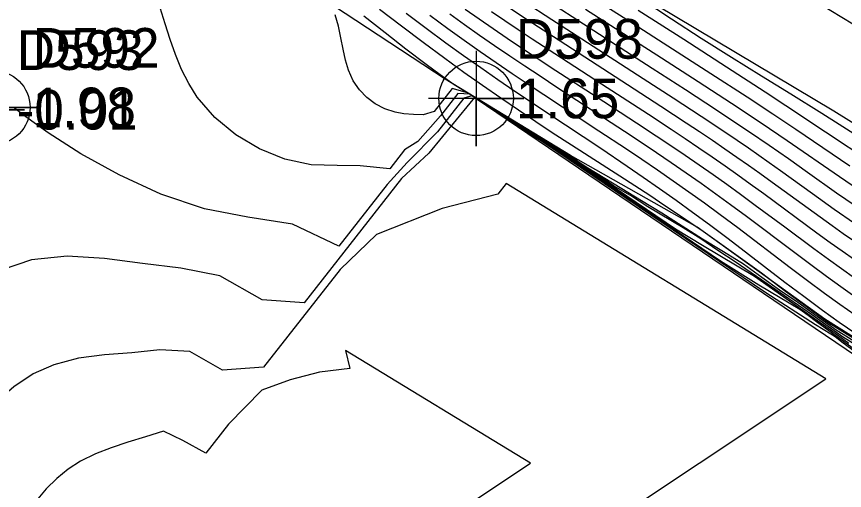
# Model space of a CAD drawing. Extents: x 2356077 to 2359823, y 225951 to 227822.
# Drawn here: x 2357257.6 to 2357309.7, y 226841 to 226870.8 of the extents above; entities that cross this region are included whole.
import ezdxf

# ---------------------------------------------------------------- set-up
doc = ezdxf.new("R2010")
doc.units = 0
for name, color, linetype in [('DTM Contours Major', 7, 'Continuous'), ('DTM Contours Minor', 7, 'Continuous'), ('Exist DTM Breakline', 7, 'Continuous'), ('Exist DTM Breakline Cogo Elevation', 7, 'Continuous'), ('Exist DTM Breakline Cogo Number', 7, 'Continuous'), ('Exist DTM Breakline Cogo Point CELL', 7, 'Continuous'), ('Exist DTM Breakline Underwater Cogo Elevation', 7, 'Continuous'), ('Exist DTM Breakline Underwater Cogo Number', 7, 'Continuous'), ('Exist DTM Breakline Underwater Cogo Point CELL', 7, 'Continuous'), ('Exist DTM Regular Point CELL', 7, 'Continuous'), ('Exist DTM Regular Point Cogo Elevation', 7, 'Continuous'), ('Exist DTM Regular Point Cogo Number', 7, 'Continuous'), ('Exist Roads EOP', 7, 'Continuous'), ('PH Exist DTM Breakline', 7, 'Continuous')]:
    doc.layers.add(name, color=color, linetype=linetype)

msp = doc.modelspace()

# ---------------------------------------------------------------- linework, layer by layer
at = {"layer": 'DTM Contours Major'}
for points in [[(2357310.359, 226856.666), (2357309.651, 226857.159), (2357308.958, 226857.65), (2357308.199, 226858.196), (2357305.194, 226860.391), (2357304.42, 226860.948), (2357303.706, 226861.454), (2357302.972, 226861.967), (2357302.214, 226862.489), (2357301.432, 226863.022), (2357300.62, 226863.567), (2357299.777, 226864.128), (2357298.178, 226865.178), (2357296.505, 226866.264), (2357291.422, 226869.548), (2357289.833, 226870.588), (2357288.221, 226871.662)], [(2357310.446, 226850.853), (2357309.405, 226851.576), (2357308.356, 226852.328), (2357307.176, 226853.2), (2357305.989, 226854.098), (2357302.421, 226856.836), (2357301.24, 226857.726), (2357300.185, 226858.504), (2357299.14, 226859.259), (2357298.104, 226859.992), (2357297.081, 226860.705), (2357296.07, 226861.397), (2357294.404, 226862.519), (2357291.071, 226864.731), (2357290.045, 226865.416), (2357289, 226866.121), (2357287.937, 226866.847), (2357286.859, 226867.595), (2357285.765, 226868.366), (2357284.658, 226869.163), (2357283.412, 226870.081), (2357282.156, 226871.023)], [(2357311.468, 226861.62), (2357308.547, 226863.556), (2357306.058, 226865.205), (2357304.744, 226866.067), (2357302.319, 226867.645), (2357299.623, 226869.385), (2357296.764, 226871.22)], [(2357310.453, 226849.817), (2357308.988, 226850.875), (2357307.985, 226851.617), (2357307.454, 226852.016), (2357306.939, 226852.385), (2357304.358, 226853.926), (2357301.946, 226855.442), (2357291.358, 226862.616), (2357290.166, 226863.342), (2357288.261, 226864.609), (2357287.686, 226864.998), (2357286.301, 226865.842), (2357285.793, 226865.69), (2357284.134, 226863.569), (2357282.214, 226861.638), (2357280.961, 226860.263), (2357277.916, 226856.371), (2357275.011, 226857.756), (2357272.202, 226858.193), (2357269.466, 226858.718), (2357266.728, 226859.655), (2357264.1, 226860.863), (2357261.695, 226862.2), (2357259.624, 226863.522), (2357258.889, 226864.032), (2357258.221, 226864.518), (2357257.445, 226865.102)]]:
    msp.add_lwpolyline(points, dxfattribs=at)
at = {"layer": 'DTM Contours Minor'}
for points in [[(2357310.072, 226861.418), (2357306.668, 226863.721), (2357305.226, 226864.684), (2357303.606, 226865.75), (2357301.338, 226867.222), (2357296.206, 226870.52), (2357293.582, 226872.203)], [(2357310.732, 226863.202), (2357308.32, 226864.719), (2357306.36, 226865.937), (2357304.513, 226867.079), (2357302.625, 226868.253), (2357300.725, 226869.453), (2357298.845, 226870.673), (2357297.017, 226871.906)], [(2357310.017, 226850.255), (2357309.29, 226850.783), (2357308.573, 226851.293), (2357307.193, 226852.259), (2357304.082, 226854.469), (2357300.814, 226856.421), (2357299.107, 226857.45), (2357291.739, 226862.442), (2357290.233, 226863.381), (2357289.056, 226864.168), (2357286.155, 226865.936), (2357285.416, 226865.988), (2357284.313, 226864.578), (2357282.899, 226862.97), (2357282.052, 226862.436), (2357281.122, 226861.248), (2357279.265, 226861.438), (2357277.824, 226861.451), (2357276.179, 226861.498), (2357274.527, 226861.858), (2357272.926, 226862.498), (2357271.435, 226863.385), (2357270.111, 226864.485), (2357269.014, 226865.765), (2357268.481, 226866.612), (2357268.032, 226867.504), (2357267.648, 226868.435), (2357267.309, 226869.396), (2357266.996, 226870.38), (2357266.689, 226871.38)], [(2357310.371, 226857.801), (2357309.093, 226858.693), (2357307.732, 226859.666), (2357305.708, 226861.125), (2357305.009, 226861.621), (2357303.691, 226862.54), (2357302.273, 226863.505), (2357300.727, 226864.535), (2357298.956, 226865.695), (2357297.074, 226866.914), (2357293.205, 226869.406), (2357291.333, 226870.617), (2357289.578, 226871.765)], [(2357310.404, 226858.92), (2357309.246, 226859.721), (2357307.421, 226861.01), (2357306.207, 226861.869), (2357304.995, 226862.713), (2357303.757, 226863.558), (2357302.405, 226864.463), (2357301.678, 226864.943), (2357299.739, 226866.209), (2357297.648, 226867.561), (2357293.32, 226870.345), (2357291.242, 226871.687)], [(2357312.313, 226848.986), (2357309.617, 226850.67), (2357307.673, 226852.084), (2357304.874, 226854.011), (2357302.851, 226855.388), (2357301.779, 226856.108), (2357300.691, 226856.831), (2357299.595, 226857.527), (2357297.362, 226858.86), (2357296.276, 226859.563), (2357295.206, 226860.178), (2357294.126, 226860.909), (2357292.994, 226861.652), (2357291.984, 226862.279), (2357290.935, 226862.99), (2357289.959, 226863.623), (2357286.008, 226866.031), (2357285.056, 226866.307), (2357283.914, 226864.847), (2357283.229, 226864.636), (2357282.61, 226864.66), (2357282.02, 226864.713), (2357281.457, 226864.814), (2357280.812, 226865.023), (2357280.218, 226865.328), (2357279.684, 226865.727), (2357279.217, 226866.215), (2357278.829, 226866.791), (2357278.527, 226867.449), (2357278.334, 226868.091), (2357278.185, 226868.777), (2357278.047, 226869.493), (2357277.891, 226870.221), (2357277.685, 226870.946)], [(2357312.587, 226848.982), (2357309.205, 226851.092), (2357308.017, 226851.955), (2357306.801, 226852.821), (2357305.644, 226853.607), (2357304.535, 226854.403), (2357303.388, 226855.247), (2357302.135, 226856.026), (2357300.807, 226856.822), (2357299.521, 226857.642), (2357298.241, 226858.446), (2357296.974, 226859.231), (2357295.729, 226859.993), (2357293.476, 226861.357), (2357291.976, 226862.37), (2357290.953, 226863.022), (2357285.179, 226866.544), (2357284.299, 226867.167), (2357283.413, 226867.815), (2357282.135, 226868.782), (2357280.827, 226869.802), (2357279.496, 226870.86)], [(2357311.766, 226849.661), (2357308.758, 226851.538), (2357307.408, 226852.521), (2357306.036, 226853.53), (2357304.526, 226854.68), (2357302.013, 226856.471), (2357300.841, 226857.295), (2357300.598, 226857.464), (2357299.422, 226858.27), (2357298.445, 226858.926), (2357297.486, 226859.56), (2357295.604, 226860.78), (2357292.563, 226862.735), (2357291.354, 226863.522), (2357290.314, 226864.208), (2357289.235, 226864.931), (2357288.12, 226865.691), (2357286.972, 226866.486), (2357285.797, 226867.318), (2357284.597, 226868.184), (2357283.238, 226869.189), (2357281.862, 226870.226), (2357280.478, 226871.284)], [(2357310.404, 226852.035), (2357309.452, 226852.703), (2357308.491, 226853.395), (2357307.409, 226854.194), (2357306.319, 226855.016), (2357303.018, 226857.527), (2357301.916, 226858.351), (2357300.925, 226859.076), (2357299.937, 226859.785), (2357298.952, 226860.478), (2357297.971, 226861.157), (2357296.994, 226861.823), (2357296.023, 226862.477), (2357294.29, 226863.625), (2357290.822, 226865.904), (2357289.831, 226866.563), (2357288.834, 226867.234), (2357287.83, 226867.919), (2357286.819, 226868.619), (2357285.802, 226869.335), (2357284.781, 226870.069), (2357283.638, 226870.909)], [(2357310.393, 226853.197), (2357309.504, 226853.821), (2357308.613, 226854.462), (2357307.614, 226855.197), (2357306.612, 226855.947), (2357303.58, 226858.234), (2357302.56, 226858.989), (2357301.638, 226859.66), (2357300.711, 226860.32), (2357299.78, 226860.973), (2357298.843, 226861.619), (2357297.901, 226862.259), (2357296.953, 226862.895), (2357295.896, 226863.594), (2357291.641, 226866.374), (2357290.583, 226867.07), (2357289.625, 226867.706), (2357288.672, 226868.346), (2357287.723, 226868.991), (2357286.779, 226869.644), (2357285.839, 226870.306), (2357284.901, 226870.978)], [(2357310.377, 226854.359), (2357309.548, 226854.941), (2357308.724, 226855.531), (2357307.807, 226856.201), (2357305.976, 226857.567), (2357304.129, 226858.947), (2357303.193, 226859.634), (2357302.341, 226860.249), (2357301.477, 226860.861), (2357300.602, 226861.471), (2357299.713, 226862.082), (2357298.808, 226862.694), (2357297.887, 226863.31), (2357296.646, 226864.129), (2357294.112, 226865.779), (2357291.579, 226867.425), (2357290.339, 226868.239), (2357289.417, 226868.85), (2357288.512, 226869.457), (2357287.623, 226870.062), (2357286.746, 226870.667), (2357285.881, 226871.274)], [(2357310.363, 226855.517), (2357309.595, 226856.055), (2357308.837, 226856.595), (2357308, 226857.202), (2357304.667, 226859.665), (2357303.814, 226860.286), (2357303.031, 226860.846), (2357302.232, 226861.409), (2357301.415, 226861.975), (2357300.577, 226862.548), (2357299.716, 226863.13), (2357298.829, 226863.721), (2357297.407, 226864.656), (2357294.454, 226866.573), (2357291.505, 226868.484), (2357290.088, 226869.412), (2357289.211, 226869.993), (2357288.36, 226870.564), (2357287.532, 226871.126)], [(2357311.012, 226859.648), (2357309.42, 226860.732), (2357306.13, 226863.01), (2357304.496, 226864.116), (2357302.632, 226865.351), (2357300.529, 226866.721), (2357298.229, 226868.205), (2357293.441, 226871.281)], [(2357310.755, 226849.47), (2357309.575, 226850.338), (2357309.15, 226850.674), (2357308.889, 226850.842), (2357307.907, 226851.429), (2357304.785, 226853.434), (2357290.982, 226862.786), (2357287.655, 226864.958), (2357287.064, 226865.348), (2357286.844, 226865.506), (2357286.448, 226865.747), (2357286.162, 226865.382), (2357283.581, 226862.241), (2357281.86, 226860.631), (2357275.741, 226852.811), (2357273.094, 226853.005), (2357270.437, 226854.506), (2357267.98, 226854.984), (2357265.571, 226855.282), (2357263.172, 226855.6), (2357260.828, 226855.744), (2357258.584, 226855.517), (2357256.731, 226854.887)], [(2357308.557, 226848.034), (2357288.458, 226860.316), (2357287.931, 226859.654), (2357284.431, 226858.758), (2357280.302, 226857.113), (2357277.999, 226854.917), (2357273.186, 226848.766), (2357270.607, 226848.576), (2357268.553, 226849.736), (2357266.653, 226849.846), (2357264.888, 226849.67), (2357263.184, 226849.53), (2357261.549, 226849.315), (2357259.991, 226848.912), (2357258.695, 226848.33), (2357257.465, 226847.525), (2357256.303, 226846.506), (2357255.209, 226845.278), (2357254.185, 226843.85), (2357253.232, 226842.229), (2357252.036, 226839.667)], [(2357289.978, 226842.71), (2357278.349, 226849.816), (2357278.619, 226848.666), (2357276.714, 226848.444), (2357274.865, 226847.966), (2357273.076, 226847.313), (2357270.978, 226845.163), (2357269.553, 226843.342), (2357268.115, 226844.15), (2357266.891, 226844.731), (2357265.749, 226844.37), (2357264.652, 226844.034), (2357263.604, 226843.688), (2357262.608, 226843.299), (2357261.668, 226842.83), (2357260.894, 226842.333), (2357260.17, 226841.753), (2357259.5, 226841.091), (2357258.887, 226840.35)], [(2357268.65, 226821.442), (2357308.557, 226848.034)], [(2357266.888, 226827.324), (2357289.978, 226842.71)]]:
    msp.add_lwpolyline(points, dxfattribs=at)
at = {"layer": 'Exist DTM Breakline'}
msp.add_lwpolyline([(2357286.558, 226865.679), (2357375.137, 226805.637)], dxfattribs=at)
at = {"layer": 'Exist DTM Breakline Cogo Point CELL'}
msp.add_lwpolyline([(2357256.15, 226868.111), (2357256.15, 226862.111), (2357256.15, 226865.111), (2357259.15, 226865.111), (2357253.15, 226865.111)], dxfattribs=at)
msp.add_circle((2357256.15, 226865.111), 2.344, dxfattribs=at)
at = {"layer": 'Exist DTM Breakline Underwater Cogo Point CELL'}
msp.add_lwpolyline([(2357255.147, 226867.969), (2357255.147, 226861.969), (2357255.147, 226864.969), (2357258.147, 226864.969), (2357252.147, 226864.969)], dxfattribs=at)
at = {"layer": 'Exist DTM Regular Point CELL'}
msp.add_lwpolyline([(2357286.558, 226868.679), (2357286.558, 226862.679), (2357286.558, 226865.679), (2357289.558, 226865.679), (2357283.558, 226865.679)], dxfattribs=at)
msp.add_circle((2357286.558, 226865.679), 2.344, dxfattribs=at)
at = {"layer": 'Exist Roads EOP'}
msp.add_lwpolyline([(2357548.158, 226751.097), (2357551.518, 226748.955), (2357539.932, 226730.044), (2357536.732, 226732.588), (2357457.094, 226780.918), (2357368.575, 226834.971), (2357285.95, 226885.112), (2357202.56, 226936.462), (2357119.743, 226986.718), (2357040.047, 227034.838), (2356959.55, 227083.993), (2356876.77, 227134.388), (2356794.33, 227184.148), (2356716.529, 227232.438), (2356632.17, 227283.448), (2356547.589, 227334.799), (2356465.16, 227384.805), (2356376.528, 227438.798), (2356293.908, 227488.913), (2356217.843, 227535.566)], dxfattribs=at)
at = {"layer": 'PH Exist DTM Breakline'}
for points in [[(2357134.751, 226970.426), (2357158.028, 226955.6), (2357176.952, 226945.122), (2357197.905, 226932.262), (2357212.892, 226921.066), (2357229.01, 226911.408), (2357243.825, 226903.007), (2357264.516, 226891.487), (2357285.525, 226878.969), (2357309.065, 226864.903), (2357332.833, 226850.108), (2357352.43, 226838.187), (2357373.686, 226825.25), (2357394.277, 226813), (2357414.012, 226801.184), (2357434.963, 226788.955), (2357455.092, 226776.87), (2357475.043, 226763.829)], [(2357329.327, 226839.832), (2357322.093, 226843.761), (2357315.282, 226847.511), (2357308.493, 226851.773), (2357300.459, 226857.57), (2357292.502, 226862.082), (2357284.62, 226866.884), (2357274.115, 226873.82), (2357265.28, 226880.04), (2357257.777, 226885.056), (2357249.936, 226888.163), (2357242.214, 226892.404), (2357235.933, 226893.489)]]:
    msp.add_lwpolyline(points, dxfattribs=at)

# ---------------------------------------------------------------- texts
at = {"layer": 'Exist DTM Breakline Cogo Elevation'}
msp.add_text('1.98', height=2.5, dxfattribs=at).set_placement((2357258.65, 226863.861))
at = {"layer": 'Exist DTM Breakline Cogo Number'}
msp.add_text('D592', height=2.5, dxfattribs=at).set_placement((2357258.65, 226867.611))
at = {"layer": 'Exist DTM Breakline Underwater Cogo Elevation'}
msp.add_text('-0.01', height=2.5, dxfattribs=at).set_placement((2357257.647, 226863.719))
at = {"layer": 'Exist DTM Breakline Underwater Cogo Number'}
msp.add_text('D593', height=2.5, dxfattribs=at).set_placement((2357257.647, 226867.469))
at = {"layer": 'Exist DTM Regular Point Cogo Elevation'}
msp.add_text('1.65', height=2.5, dxfattribs=at).set_placement((2357289.058, 226864.429))
at = {"layer": 'Exist DTM Regular Point Cogo Number'}
msp.add_text('D598', height=2.5, dxfattribs=at).set_placement((2357289.058, 226868.179))

doc.saveas('drawing.dxf')
